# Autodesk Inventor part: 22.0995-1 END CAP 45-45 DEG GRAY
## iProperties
Created: 2007-01
Part Number: 22.0995-1 END CAP 45-45 DEG GRAY
Document SubType Name: Modeling
Designer: Andy Moles
Material: ABS Plastic
Density: 1.06 g/cm^3
Mass: 6.14711 g
Surface Area: 51.8226 cm^2
Volume: 5.79916 cm^3
Description: END CAP 45X45 DEG GRAY
Vendor: S
Author: Andy Moles
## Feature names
1. Extrusion1
2. Fillet1
3. Fillet2
4. Fillet3
5. Extrusion2
6. Fillet4
7. Hole1
